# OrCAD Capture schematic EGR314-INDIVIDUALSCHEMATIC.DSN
size A; title: JC Reed - EGR314 - Individual Schematic - HMI; rev: 1; note: 1
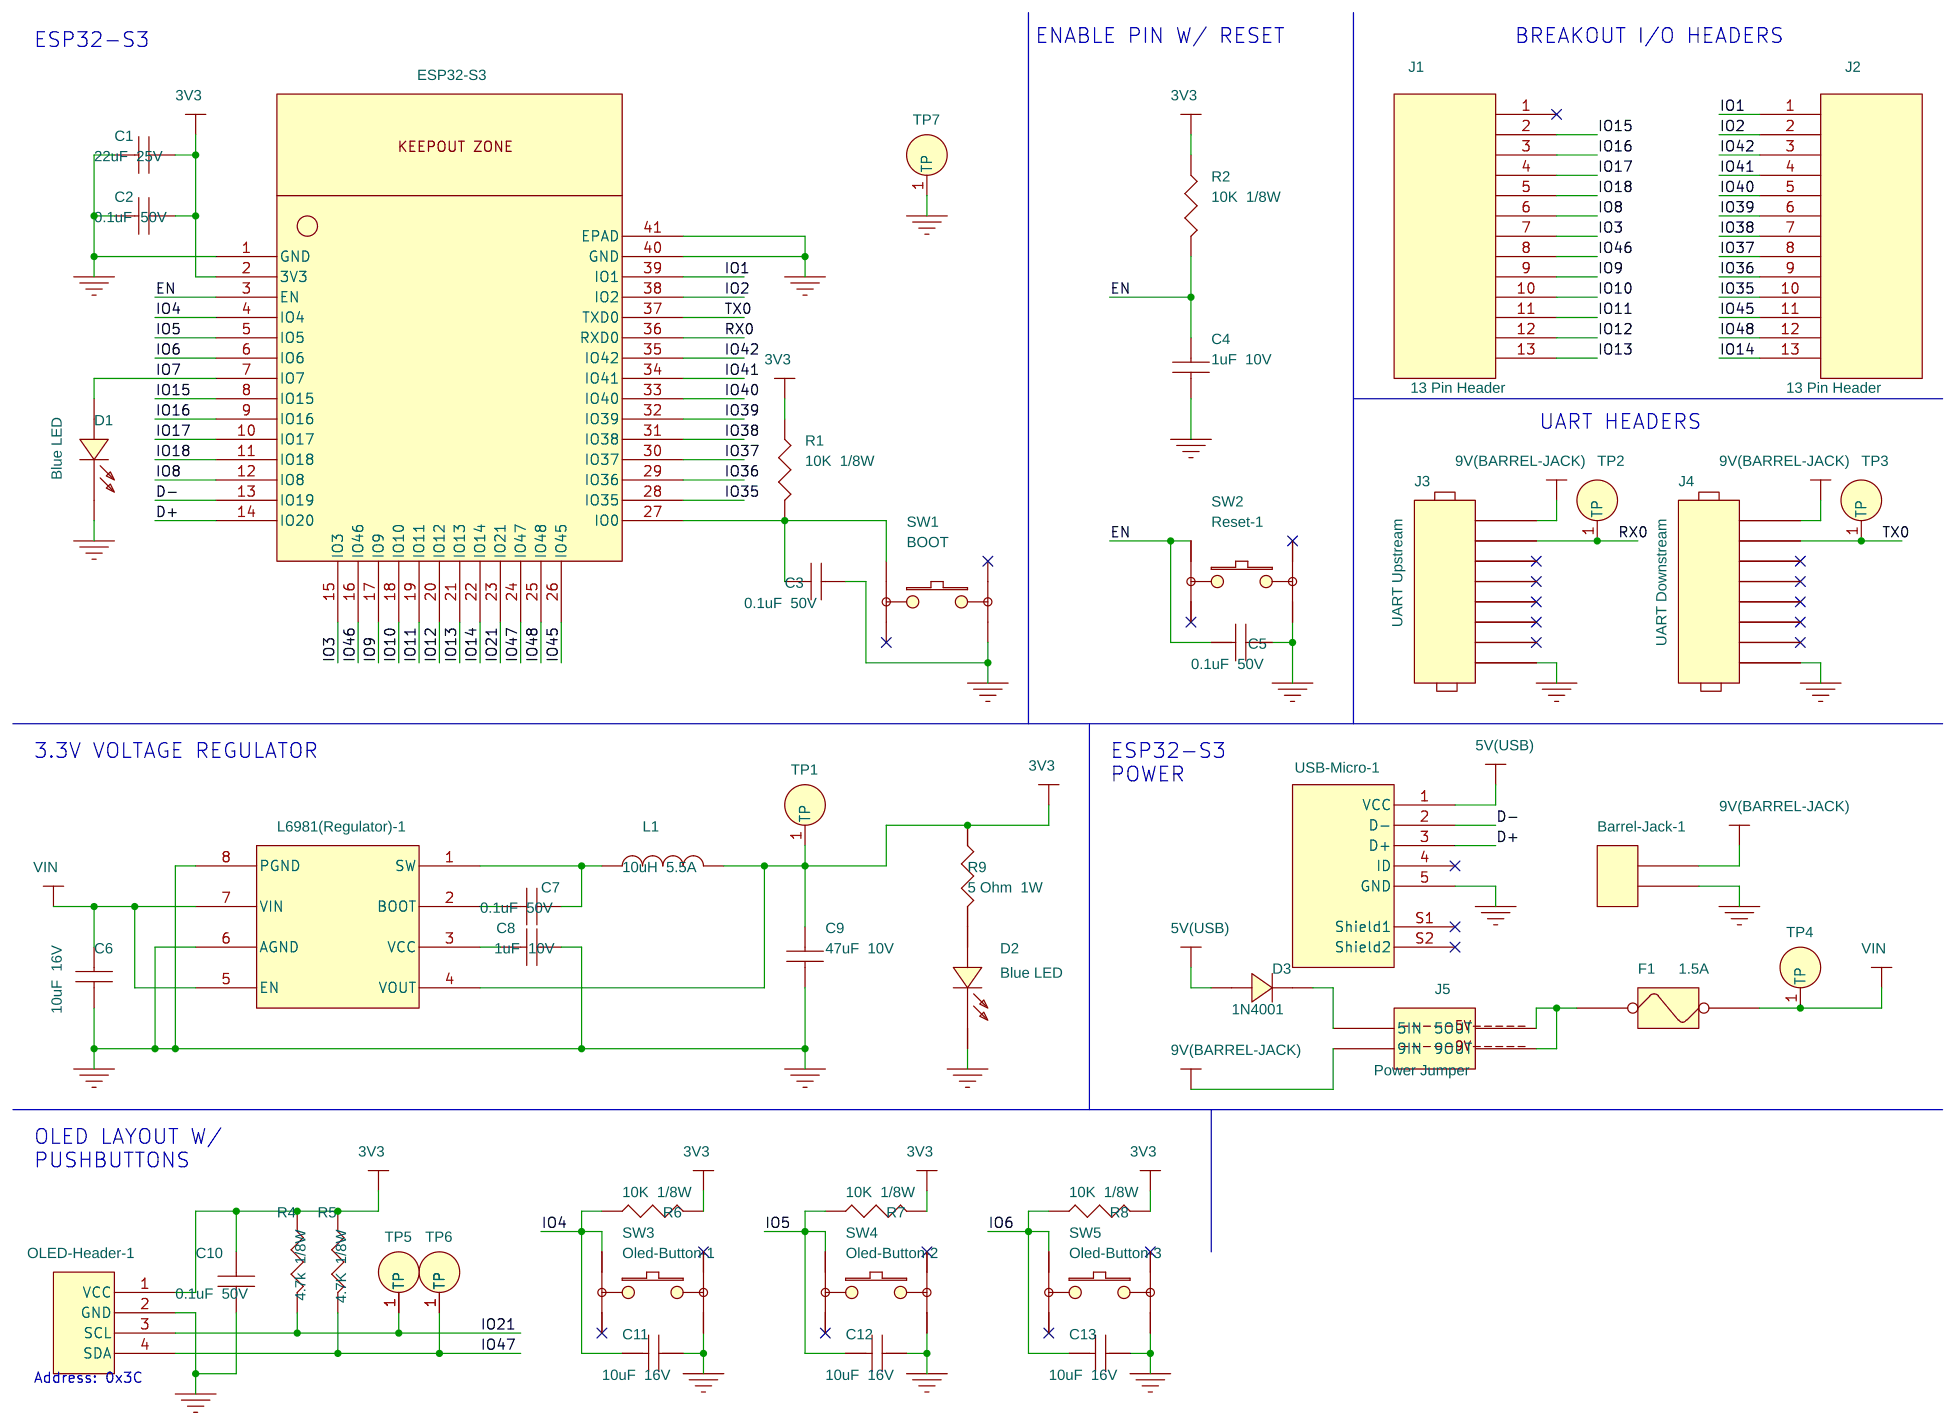
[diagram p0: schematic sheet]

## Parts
Barrel-Jack-1  CON2_M  [CUI_PJ-102A]
C1  22uF  25V  [smc1206]
C2  0.1uF  50V  [smc0805]
C3  0.1uF  50V  [smc0805]
C4  1uF  10V  [smc0805]
C5  0.1uF  50V  [smc0805]
C6  10uF  16V  [smc0805]
C7  0.1uF  50V  [smc0805]
C8  1uF  10V  [smc0805]
C9  47uF  10V  [smc0805]
C10  0.1uF  50V  [smc0805]
C11  10uF  16V  [smc0805]
C12  10uF  16V  [smc0805]
C13  10uF  16V  [smc0805]
D1  Blue LED  [smc1206]
D2  Blue LED  [smc1206]
D3  1N4001  [smdo214ac]
ESP32-S3  ESP32-S3  [XCVR_ESP32-S3-WROOM-1-N4]
F1  1.5A  [smr0603]
J1  13 Pin Header  [SAMTEC_TSW-113-17-G-S]
J2  13 Pin Header  [SAMTEC_TSW-113-17-G-S]
J3  UART Upstream  [JUMPER8]
J4  UART Downstream  [JUMPER8]
J5  Power Jumper  [TE_826656-2]
L1  10uH  5.5A  [Inductor]
L6981(Regulator)-1  L6981C33DR  [SOIC127P600X175-8N]
OLED-Header-1  OLED-Header  [JUMPER4]
R1  10K  1/8W  [smr0805]
R2  10K  1/8W  [smr0805]
R4  4.7k  1/8W  [smr0805]
R5  4.7K  1/8W  [smr0805]
R6  10K  1/8W  [smr0805]
R7  10K  1/8W  [smr0805]
R8  10K  1/8W  [smr0805]
R9  5 Ohm  1W  [smr2512]
SW1  BOOT  [Button]
SW2  Reset-1  [Button]
SW3  Oled-Button-1  [Button]
SW4  Oled-Button-2  [Button]
SW5  Oled-Button-3  [Button]
TP1  Test Point  [KEYSTONE_5006]
TP2  Test Point  [KEYSTONE_5006]
TP3  Test Point  [KEYSTONE_5006]
TP4  Test Point  [KEYSTONE_5006]
TP5  Test Point  [KEYSTONE_5006]
TP6  Test Point  [KEYSTONE_5006]
TP7  Test Point  [KEYSTONE_5006]
USB-Micro-1  USB-Micro  [GCT_USB3131-30-0230-A_REVB]

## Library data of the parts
Barrel-Jack-1 = CON2_M
C1-C13 = CAP_NP
D1 D2 = LED
D3 = DIODE
ESP32-S3 = ESP32-S3
F1 = FUSEHOLDER
J1 J2 = 13_Pin_Header
J3 J4 = 8_HEADER
J5 = Power_Jumper
L1 = INDUCTOR
L6981(Regulator)-1 = L6981C33DR_0
OLED-Header-1 = OLED-Header
R1 R2 R4-R9 = R
SW1-SW5 = SW_TACT-SPST-2
TP1-TP7 = Test_Point
USB-Micro-1 = USB-Micro

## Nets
3V3: C1.2 C2.2 C9.1 C10.1 ESP32-S3.2(3V3) L1.1 L6981(Regulator)-1.4(VOUT) OLED-Header-1.1(VCC) R1.1 R2.1 R4.1 R5.1 R6.2 R7.2 R8.2 R9.1 TP1.1(TP)
5V(USB): D3.2(A) USB-Micro-1.1(VCC)
9V(Barrel-Jack): Barrel-Jack-1.1 J3.1 J4.1 J5.3(9IN)
GND: Barrel-Jack-1.2 C1.1 C2.1 C3.1 C4.2 C5.2 C6.2 C8.1 C9.2 C10.2 C11.1 C12.1 C13.1 D1.1(CATHODE) D2.1(CATHODE) ESP32-S3.1(GND) ESP32-S3.40(GND) ESP32-S3.41(EPAD) J3.8 J4.8 L6981(Regulator)-1.6(AGND) L6981(Regulator)-1.8(PGND) OLED-Header-1.2(GND) SW1.3 SW2.3 SW3.3 SW4.3 SW5.3 TP7.1(TP) USB-Micro-1.5(GND)
Vin: C6.1 F1.2 L6981(Regulator)-1.5(EN) L6981(Regulator)-1.7(VIN) TP4.1(TP)
D+: ESP32-S3.14(IO20) USB-Micro-1.3(D+)
D-: ESP32-S3.13(IO19) USB-Micro-1.2(D-)
EN: C4.1 C5.1 ESP32-S3.3(EN) R2.2 SW2.1
IO1: ESP32-S3.39(IO1) J2.1
IO2: ESP32-S3.38(IO2) J2.2
IO3: ESP32-S3.15(IO3) J1.7
IO4: C11.2 ESP32-S3.4(IO4) R6.1 SW3.1
IO5: C12.2 ESP32-S3.5(IO5) R7.1 SW4.1
IO6: C13.2 ESP32-S3.6(IO6) R8.1 SW5.1
IO7: D1.2(ANODE) ESP32-S3.7(IO7)
IO8: ESP32-S3.12(IO8) J1.6
IO9: ESP32-S3.17(IO9) J1.9
IO10: ESP32-S3.18(IO10) J1.10
IO11: ESP32-S3.19(IO11) J1.11
IO12: ESP32-S3.20(IO12) J1.12
IO13: ESP32-S3.21(IO13) J1.13
IO14: ESP32-S3.22(IO14) J2.13
IO15: ESP32-S3.8(IO15) J1.2
IO16: ESP32-S3.9(IO16) J1.3
IO17: ESP32-S3.10(IO17) J1.4
IO18: ESP32-S3.11(IO18) J1.5
IO21: ESP32-S3.23(IO21) OLED-Header-1.3(SCL) R4.2 TP5.1(TP)
IO35: ESP32-S3.28(IO35) J2.10
IO36: ESP32-S3.29(IO36) J2.9
IO37: ESP32-S3.30(IO37) J2.8
IO38: ESP32-S3.31(IO38) J2.7
IO39: ESP32-S3.32(IO39) J2.6
IO40: ESP32-S3.33(IO40) J2.5
IO41: ESP32-S3.34(IO41) J2.4
IO42: ESP32-S3.35(IO42) J2.3
IO45: ESP32-S3.26(IO45) J2.11
IO46: ESP32-S3.16(IO46) J1.8
IO47: ESP32-S3.24(IO47) OLED-Header-1.4(SDA) R5.2 TP6.1(TP)
IO48: ESP32-S3.25(IO48) J2.12
RX0: ESP32-S3.36(RXD0) J3.2 TP2.1(TP)
TX0: ESP32-S3.37(TXD0) J4.2 TP3.1(TP)
N00680: C7.1 L1.2 L6981(Regulator)-1.1(SW)
N00714: C7.2 L6981(Regulator)-1.2(BOOT)
N00777: C8.2 L6981(Regulator)-1.3(VCC)
N03282: F1.1 J5.2(5OUT) J5.4(9OUT)
N03524: D3.1(K) J5.1(5IN)
N50777: C3.2 ESP32-S3.27(IO0) R1.2 SW1.1
N54924: D2.2(ANODE) R9.2

Not connected (* = marked no-connect by the designer): J1 1*; J3 3* 4* 5* 6* 7*; J4 3* 4* 5* 6* 7*; SW1 2* 4*; SW2 2* 4*; SW3 2* 4*; SW4 2* 4*; SW5 2* 4*; USB-Micro-1 4(ID)* S1(Shield1)* S2(Shield2)*

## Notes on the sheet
- ESP32-S3
- ENABLE PIN W/ RESET
- BREAKOUT I/O HEADERS
- UART HEADERS
- 3.3V VOLTAGE REGULATOR
- ESP32-S3
  POWER
- OLED LAYOUT W/
  PUSHBUTTONS
- Address: 0x3C
